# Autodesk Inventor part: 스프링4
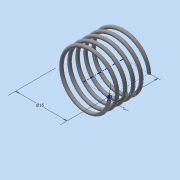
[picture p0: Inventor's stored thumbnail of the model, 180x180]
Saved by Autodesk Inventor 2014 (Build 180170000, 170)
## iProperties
Created: 2015-06
Part Number: 스프링4
Material: 강철, 연강
Document SubType Name: Modeling
Designer: MYHOME
Density: 7.86 g/cm^3
Appearance: 강철
Mass: 1.52623 g
Surface Area: 7.86279 cm^2
Volume: 0.194177 cm^3
Author: MYHOME
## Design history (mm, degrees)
sketch "스케치1"
  geometry: L1 (0, 0)-(8, 0); L2 (8, 0)-(8, 12.5); L3 (8, 12.5)-(0, 12.5); L4 (0, 12.5)-(0, 0); C1 r 0.5 at (8, 0)
  constraints: 8 end point, 2 parallel, 1 centre point, 1 coincident, 1 horizontal, 1 perpendicular
  dimensions: "d0" = 16 diameter of L2 L4; "d1" = 12.5 distance of L1.end L2.end (derived); "d2" = 1 diameter of C1
feature "코일1" sketch "스케치1" pitch "d3" = 10; turns "d5" = 5; dims "d4" = 12.5 (= d1), "d6" = 0, angle "d7" = 90 deg, angle "d8" = 90 deg, "d9" = 0, "d10" = 0
node "작업 평면1"
sketch "스케치2"
  geometry: L1 (-8.5, 0)-(-7.5, 0) reference; 1 further point
  constraints: 1 horizontal alignment
extrude "돌출1" cut sketch "스케치2" stored distance "d12" = 10; taper "d13" = 0 deg
node "작업 평면2"
sketch "스케치3"
  geometry: L1 (8.5, 0)-(7.5, 0) reference; 1 further point
  constraints: 1 horizontal alignment
extrude "돌출2" cut sketch "스케치3" stored distance "d15" = 10; taper "d16" = 0 deg
node "솔리드1"
node "절단 모서리 투영1"
node "절단 모서리 투영2"
other parameters: "d11" = 0, "d14" = -12.5 (= -d1)
